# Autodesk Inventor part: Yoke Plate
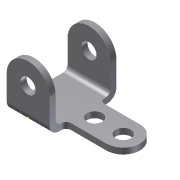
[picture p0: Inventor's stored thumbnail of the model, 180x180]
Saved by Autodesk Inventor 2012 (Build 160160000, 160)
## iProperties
Created: 2011-04
Part Number: Yoke Plate
Material: Default
Document SubType Name: Modeling
Designer: Dell
Density: 1 g/cm^3
Author: Dell
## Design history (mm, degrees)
sketch "Sketch1"
  geometry: 1 further point
sketch "Sketch2"
  geometry: L1 (28.578, 36.513)-(28.483, -7.913); L2 (-28.517, -7.961)-(28.483, -7.913); L3 (-28.554, 36.476)-(-28.517, -7.961); C1 r 10 at (0.012, 36.5); A1 r 28.566 centre (0.012, 36.5) between (28.578, 36.513) and (-28.554, 36.476); 2 further points
  constraints: 6 end point, 2 centre point, 2 point on circle, 1 coincident, 1 perpendicular, 1 tangent, 1 other
  dimensions: "d0" = 57 distance of L2.start L1.end; "d1" = 36.5 distance of point (0, 0) C1.centre; "d2" = 28.5 distance from line of L1 point (0, 0); "d3" = 20 diameter of C1
extrude "Extrusion1" new body sketch "Sketch2" distance "d4" = 89; taper "d5" = 0 deg
sketch "Sketch3"
  geometry: L1 (44.437, 89)-(0, 89) reference; L2 (-28.588, 8)-(36.5, 8); L3 (36.5, 8)-(36.5, 81); L4 (36.5, 81)-(-28.588, 81); L5 (-28.588, 8)-(-28.588, 81); L6 (-28.566, 89)-(0.011, 89) reference; 3 further points
  constraints: 8 end point, 1 perpendicular
  dimensions: "d6" = 73 distance of L2.start L4.end; "d9" = 8 distance between parallel lines of L1 L4
extrude "Extrusion2" cut sketch "Sketch3" distance "d10" = 89; taper "d11" = 0 deg
sketch "Sketch4"
  geometry: L1 (0, 58.725)-(53.5, 58.725); L2 (53.5, 14.225)-(0, 14.225); L3 (0, 14.225)-(0, 58.725); C1 r 10 at (53.5, 36.475); C2 r 10 at (15.5, 36.513); A1 r 22.25 centre (53.5, 36.475) between (53.5, 14.225) and (53.5, 58.725); 1 further point
  constraints: 6 end point, 3 centre point, 2 point on circle, 1 coincident, 1 equal radius, 1 horizontal, 1 parallel, 1 perpendicular, 1 tangent
  dimensions: "d12" = 44.5 diameter of A1; "d13" = 44.5 distance between parallel lines of L2 L1; "d14" = 20 diameter of C1; "d15" = 38 distance of A1.centre C2.centre
extrude "Extrusion3" join sketch "Sketch4" stored distance "d16" = 89; taper "d17" = 0 deg
fillet "Fillet1" dims "d18" = 12.7
fillet "Fillet2" dims "d19" = 6.35
fillet "Fillet3" dims "d20" = 6.35
body "Solid1"
